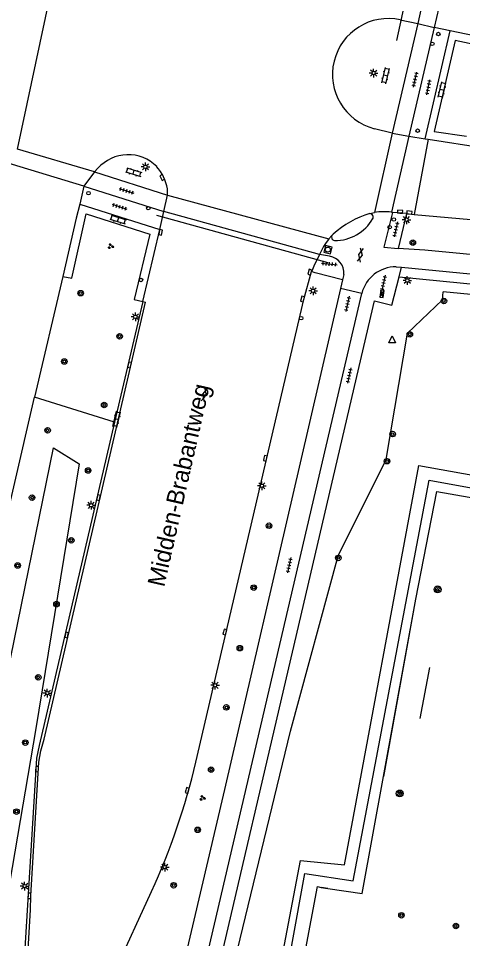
# Model space of a CAD drawing. Extents: x 130998 to 133001, y 398999 to 403002.
# Drawn here: x 132831.9 to 132896.2, y 399348.3 to 399481.4 of the extents above; entities that cross this region are included whole.
import ezdxf

# ---------------------------------------------------------------- set-up
doc = ezdxf.new("R2010")
doc.units = 0
for name, color, linetype in [('bs-afsc-ballenvanger', 7, 'Continuous'), ('bs-afsc-doel', 7, 'Continuous'), ('bs-afsc-poort', 7, 'Continuous'), ('bs-symb-sproeier', 7, 'Continuous'), ('gg-afsc-hekwerk', 7, 'Continuous'), ('gg-anno-openbare ruimte label', 7, 'Continuous'), ('gg-knt-verharding', 7, 'Continuous'), ('gg-knt-verharding nz', 7, 'Continuous'), ('gt-grn-groengrens', 7, 'Continuous'), ('gt-grn-weggrens', 7, 'Continuous'), ('gt-grn-weggrens revisie', 7, 'Continuous'), ('gt-knt-lijn portaal', 7, 'Continuous'), ('gt-symb-boom', 7, 'Continuous'), ('gt-symb-drukknoppaal', 7, 'Continuous'), ('gt-symb-gesloten verharding', 7, 'Continuous'), ('gt-symb-groenvak', 7, 'Continuous'), ('gt-symb-klinker verharding', 7, 'Continuous'), ('gt-symb-kolk', 7, 'Continuous'), ('gt-symb-lichtmast', 7, 'Continuous'), ('gt-symb-rioolschacht', 7, 'Continuous'), ('gt-symb-tegel verharding', 7, 'Continuous'), ('gt-symb-verkeersregelinstallatiekast', 7, 'Continuous'), ('gt-symb-verkeersregelinstallatiepaal', 7, 'Continuous'), ('gt-symb-waterafsluiter', 7, 'Continuous')]:
    doc.layers.add(name, color=color, linetype=linetype)

# ---------------------------------------------------------------- blocks, each defined once
blk = doc.blocks.new('gt0-KL1')
at = {"layer": 'gt-symb-klinker verharding'}
for p, q in [((-1.15, 0.3), (1.15, 0.3)), ((-1, -0.3), (-1, 0.3)), ((-0.5, 0.3), (-0.5, 0.45)), ((0, -0.3), (0, 0.3)), ((0.5, 0.3), (0.5, 0.45)), ((1, -0.3), (1, 0.3)), ((-1.15, -0.3), (1.15, -0.3)), ((-0.5, -0.45), (-0.5, -0.3)), ((0.5, -0.45), (0.5, -0.3))]:
    blk.add_line(p, q, dxfattribs=at)
blk = doc.blocks.new('gt0-TEG1')
at = {"layer": 'gt-symb-tegel verharding'}
for p, q in [((-1.12, 0), (1.12, 0)), ((-0.9, -0.25), (-0.9, 0.25)), ((-0.45, -0.25), (-0.45, 0.25)), ((0, -0.25), (0, 0.25)), ((0.45, -0.25), (0.45, 0.25)), ((0.9, -0.25), (0.9, 0.25))]:
    blk.add_line(p, q, dxfattribs=at)
blk = doc.blocks.new('gt0-LMAST')
at = {"layer": 'gt-symb-lichtmast'}
for p, q in [((-0.18, 0.17), (-0.45, 0.44)), ((-0.01, 0.25), (-0.01, 0.62)), ((0.17, 0.17), (0.44, 0.44)), ((-0.26, 0), (-0.63, 0)), ((-0.18, -0.18), (-0.45, -0.45)), ((-0.01, -0.25), (-0.01, -0.63)), ((0.44, -0.45), (0.17, -0.18)), ((0.24, 0), (0.62, 0))]:
    blk.add_line(p, q, dxfattribs=at)
blk.add_circle((-0.01, 0), 0.25, dxfattribs=at)
blk = doc.blocks.new('gt0-DPAAL')
at = {"layer": 'gt-symb-drukknoppaal'}
blk.add_circle((0, 0), 0.25, dxfattribs=at)
blk = doc.blocks.new('gt0-VIPAAL')
at = {"layer": 'gt-symb-verkeersregelinstallatiepaal'}
blk.add_circle((0, 0), 0.25, dxfattribs=at)
blk = doc.blocks.new('gt0-KOLK')
at = {"layer": 'gt-symb-kolk'}
blk.add_lwpolyline([(0, 0), (0.37, 0), (0.37, 0.4), (-0.38, 0.4), (-0.38, 0), (0, 0)], dxfattribs=at)
blk = doc.blocks.new('gt0-RS')
at = {"layer": 'gt-symb-rioolschacht'}
blk.add_lwpolyline([(-0.5, -0.5), (0.5, -0.5), (0.5, 0.5), (-0.5, 0.5)], close=True, dxfattribs=at)
blk.add_circle((0, 0), 0.375, dxfattribs=at)
blk = doc.blocks.new('gt0-GESVH1')
at = {"layer": 'gt-symb-gesloten verharding'}
for p, q in [((-0.99, -0.26), (0.01, 0.24)), ((0.01, -0.26), (-0.99, 0.24)), ((0.01, 0.24), (1.01, -0.26)), ((1.01, 0.24), (0.01, -0.26))]:
    blk.add_line(p, q, dxfattribs=at)
blk = doc.blocks.new('gt0-BOOM')
at = {"layer": 'gt-symb-boom'}
for radius in [0.4, 0.2]:
    blk.add_circle((0, 0), radius, dxfattribs=at)
blk = doc.blocks.new('gt0-GRVAK')
at = {"layer": 'gt-symb-groenvak'}
for p, q in [((-0.11, 0.19), (-0.23, 0.24)), ((-0.18, 0.15), (0.09, 0.15)), ((-0.09, 0.21), (-0.16, 0.32)), ((-0.05, 0.21), (-0.05, 0.39)), ((0, 0.21), (0.06, 0.32)), ((0.01, 0.19), (0.13, 0.24)), ((0.26, -0.05), (0.2, 0.06)), ((0.3, -0.05), (0.3, 0.13)), ((0.35, -0.05), (0.41, 0.06)), ((-0.24, -0.23), (-0.36, -0.18)), ((-0.32, -0.26), (-0.05, -0.26)), ((-0.23, -0.21), (-0.29, -0.09)), ((-0.18, -0.2), (-0.18, -0.02)), ((-0.14, -0.21), (-0.07, -0.09)), ((-0.12, -0.23), (0, -0.18)), ((0.24, -0.07), (0.12, -0.02)), ((0.17, -0.11), (0.44, -0.11)), ((0.37, -0.07), (0.49, -0.02))]:
    blk.add_line(p, q, dxfattribs=at)
blk = doc.blocks.new('gt0-VRIKST')
at = {"layer": 'gt-symb-verkeersregelinstallatiekast'}
for p, q in [((-0.5, -0.25), (0.5, 0.25)), ((-0.5, 0.25), (0.5, -0.25))]:
    blk.add_line(p, q, dxfattribs=at)
blk.add_lwpolyline([(0.5, 0.25), (-0.5, 0.25), (-0.5, -0.25), (0.5, -0.25)], close=True, dxfattribs=at)
blk = doc.blocks.new('gt0-WAFSL')
at = {"layer": 'gt-symb-waterafsluiter'}
for p, q in [((-0.5, -0.33), (0, 0.67)), ((0, 0.67), (0.5, -0.33)), ((0.5, -0.33), (-0.5, -0.33))]:
    blk.add_line(p, q, dxfattribs=at)
blk = doc.blocks.new('bs0-SPROEIER')
at = {"layer": 'bs-symb-sproeier'}
for p, q in [((-0.34, 0.2), (0.2, -0.34)), ((-0.21, 0.35), (0.34, -0.2)), ((0.03, 0.4), (0.4, 0.03)), ((-0.4, -0.03), (-0.03, -0.4))]:
    blk.add_line(p, q, dxfattribs=at)
blk.add_circle((0, 0), 0.5, dxfattribs=at)

msp = doc.modelspace()

# ---------------------------------------------------------------- linework, layer by layer
at = {"layer": 'bs-afsc-ballenvanger'}
msp.add_line((132884.76, 399371.7), (132889.37, 399397.36), dxfattribs=at)
at = {"layer": 'bs-afsc-doel'}
msp.add_line((132890.01, 399380.09), (132891.4, 399387.46), dxfattribs=at)
at = {"layer": 'bs-afsc-poort'}
msp.add_line((132875.68, 399355.68), (132876.66, 399355.53), dxfattribs=at)
at = {"layer": 'gg-afsc-hekwerk'}
msp.add_line((132876.66, 399355.53), (132875.68, 399355.68), dxfattribs=at)
for points in [[(132889.37, 399397.36), (132892.4, 399412.94), (132925.72, 399407.1)], [(132876.66, 399355.53), (132881.63, 399354.77), (132889.37, 399397.36)], [(132863.07, 399291.46), (132875.15, 399355.78), (132875.68, 399355.68)]]:
    msp.add_lwpolyline(points, dxfattribs=at)
at = {"layer": 'gg-knt-verharding'}
for p, q in [((132887.12, 399481.18), (132889.68, 399480.63)), ((132889.68, 399480.63), (132885.96, 399464.75)), ((132892.06, 399480.08), (132888.38, 399464.33)), ((132889.68, 399480.63), (132892.06, 399480.08)), ((132894.36, 399479.6), (132892.06, 399480.08)), ((132890.71, 399463.97), (132894.36, 399479.6)), ((132904.81, 399477.39), (132894.36, 399479.6)), ((132885.96, 399464.75), (132883.38, 399465.42)), ((132885.96, 399464.75), (132888.38, 399464.33)), ((132888.38, 399464.33), (132890.71, 399463.97)), ((132890.71, 399463.97), (132891.19, 399463.9)), ((132891.19, 399463.9), (132901.04, 399462.38)), ((132843.38, 399459.7), (132842.87, 399459.18)), ((132842.87, 399459.18), (132841.36, 399457.11)), ((132842.87, 399459.18), (132853.47, 399455.79)), ((132841.36, 399457.11), (132840.75, 399454.5)), ((132841.36, 399457.11), (132852.94, 399453.43)), ((132852.94, 399453.43), (132853.47, 399455.79)), ((132853.47, 399455.79), (132853.47, 399456.73)), ((132840.75, 399454.5), (132852.35, 399450.84)), ((132852.35, 399450.84), (132852.94, 399453.43)), ((132888.01, 399453.13), (132886.02, 399453.32)), ((132888.01, 399453.13), (132886.85, 399448.1)), ((132888.01, 399453.13), (132889.15, 399453.03)), ((132849.87, 399440.41), (132852.35, 399450.84)), ((132877.43, 399450.16), (132877.22, 399449.95)), ((132877.47, 399449.29), (132877.63, 399449.25)), ((132876.9, 399446.97), (132875.44, 399447.21)), ((132886.52, 399445.45), (132887.3, 399445.38)), ((132838.29, 399444.06), (132834.22, 399426.59)), ((132878.97, 399444.35), (132878.78, 399443.55)), ((132886.95, 399443.97), (132939.03, 399438.92)), ((132878.78, 399443.55), (132878.48, 399442.29)), ((132846.17, 399289.96), (132881.56, 399441.59)), ((132878.48, 399442.29), (132872.63, 399417.07)), ((132881.56, 399441.59), (132878.48, 399442.29)), ((132849.87, 399440.41), (132845.79, 399422.95)), ((132849.87, 399440.41), (132850.28, 399440.31))]:
    msp.add_line(p, q, dxfattribs=at)
for points in [[(132904.81, 399477.39), (132904.51, 399476.16), (132895.09, 399478.2), (132892.04, 399465.01), (132896.73, 399464.33)], [(132840.75, 399454.5), (132840.24, 399452.47), (132838.29, 399444.06)], [(132838.29, 399444.06), (132839.61, 399443.78), (132841.68, 399453.12), (132850.91, 399450.18), (132848.62, 399440.7), (132849.87, 399440.41)], [(132886.02, 399453.32), (132884.77, 399448.28), (132886.85, 399448.1)], [(132889.15, 399453.03), (132905.03, 399451.62), (132922.15, 399450.06)], [(132916.23, 399445.37), (132901.79, 399446.8), (132890.67, 399447.85), (132886.85, 399448.1)], [(132875.44, 399447.21), (132874.63, 399445.55), (132874.31, 399444.83), (132874.29, 399444.75)], [(132887.3, 399445.38), (132939.45, 399440.33), (132957.32, 399437.98), (132974.21, 399435.67), (132990.03, 399433.38), (133000, 399431.89)], [(132848.15, 399289.52), (132883.39, 399440.5), (132885.93, 399439.9), (132886.95, 399443.97)], [(132857.54, 399373.78), (132873.2, 399440.72), (132874.29, 399444.75)], [(132878.78, 399443.55), (132874.8, 399444.59), (132874.29, 399444.75)], [(132831.89, 399331.89), (132832.43, 399331.86), (132833.61, 399352.42), (132833.67, 399354.45), (132834.83, 399373.77), (132835.14, 399375.45), (132835.58, 399377.1), (132847.93, 399430.32), (132850.28, 399440.31)], [(132762.64, 399000), (132764.86, 399018.61), (132773.1, 399080.84), (132777.39, 399111.89), (132787.45, 399180.57), (132799.49, 399253.49), (132821.57, 399368.18), (132821.05, 399368.32), (132828.33, 399401.27), (132834.22, 399426.59)], [(132845.79, 399422.95), (132834.86, 399376.22), (132834.48, 399374.36), (132831.89, 399331.89)], [(132872.63, 399417.07), (132861.68, 399369.83), (132843.19, 399290.95)], [(132772.83, 399000), (132775.07, 399017.52), (132784.71, 399079.82), (132793.52, 399126.23), (132804.32, 399176.71), (132840.62, 399332.15), (132851.14, 399355.1)]]:
    msp.add_lwpolyline(points, dxfattribs=at)
for centre, radius, start, end in [((132885.42, 399473.26), 8.1, 77.84, 166.2632), ((132885.42, 399473.26), 8.1, 166.2849, 255.411), ((132847.76, 399455.82), 5.84, 45.0487, 138.4289), ((132846.25, 399455.18), 7.38, 12.1299, 40.3162), ((132886.66, 399439.98), 13.74, 106.552, 132.2085), ((132882.7, 399452.65), 0.508, 331.076, 84.2901), ((132877.7, 399455.53), 6.28, 269.4295, 330.1834), ((132877.67, 399449.74), 0.497, 154.988, 246.6135), ((132876.54, 399444.56), 2.44, 354.9696, 81.5951), ((132886.51, 399440.35), 5.1, 89.9511, 165.903), ((132761.39, 399396.27), 98.75, 335.3566, 346.836)]:
    msp.add_arc(centre, radius, start, end, dxfattribs=at)
at = {"layer": 'gg-knt-verharding nz'}
for p, q in [((132892.98, 399496.5), (132889.68, 399480.63)), ((132895.51, 399495.14), (132892.06, 399480.08)), ((132885.96, 399464.75), (132883.4, 399453.29)), ((132888.38, 399464.33), (132885.85, 399453.34)), ((132842.87, 399459.18), (132831.72, 399462.47)), ((132841.36, 399457.11), (132829.43, 399460.7)), ((132853.47, 399455.79), (132876.79, 399449.47)), ((132875.44, 399447.21), (132852.94, 399453.43)), ((132882.75, 399453.15), (132883.4, 399453.29)), ((132885.85, 399453.34), (132886.02, 399453.32)), ((132877.22, 399449.95), (132876.79, 399449.47))]:
    msp.add_line(p, q, dxfattribs=at)
for centre, radius, start, end in [((132884.79, 399445.17), 8.24, 82.5999, 99.6925), ((132883.48, 399443.96), 8.67, 140.4841, 157.954)]:
    msp.add_arc(centre, radius, start, end, dxfattribs=at)
at = {"layer": 'gt-grn-groengrens'}
msp.add_line((132845.79, 399422.95), (132834.22, 399426.59), dxfattribs=at)
for points in [[(132846.79, 399277.41), (132871.24, 399378.25), (132878.15, 399403.62), (132885.09, 399417.58), (132888.18, 399435.85), (132893.23, 399440.68), (132893.34, 399441.82)], [(132968.46, 399433.54), (132938.54, 399437.48), (132893.34, 399441.82)], [(132846.79, 399277.41), (132849.47, 399276.97), (132849.56, 399277.12), (132850.42, 399278.24), (132851.9, 399278.69), (132853.73, 399278.33), (132854.18, 399276.39), (132856.78, 399275.98), (132872.7, 399359.57), (132879.05, 399358.94), (132889.84, 399416.71), (132961.48, 399403.86), (132963.58, 399415.25), (132974.36, 399413.48), (132975.53, 399419.89), (132980.55, 399418.98), (132980.57, 399419.09)], [(132802.26, 399226.05), (132797.53, 399226.68), (132817.25, 399322.97), (132836.97, 399419.26), (132840.67, 399416.95), (132834.38, 399378.64), (132823.69, 399316.06), (132819.29, 399291.8), (132802.26, 399226.05)], [(132858.19, 399274.24), (132873.33, 399357.67), (132880.32, 399356.61), (132891.32, 399414.6), (132962.62, 399401.59)]]:
    msp.add_lwpolyline(points, dxfattribs=at)
at = {"layer": 'gt-grn-weggrens'}
for p, q in [((132831.72, 399462.47), (132841.4, 399507.69)), ((132886.95, 399443.97), (132887.3, 399445.38))]:
    msp.add_line(p, q, dxfattribs=at)
at = {"layer": 'gt-grn-weggrens revisie'}
msp.add_line((132891.19, 399463.9), (132889.15, 399453.03), dxfattribs=at)
at = {"layer": 'gt-knt-lijn portaal'}
for p, q in [((132886.64, 399478.2), (132891.24, 399499.17)), ((132851.87, 399452.89), (132876.65, 399446.07))]:
    msp.add_line(p, q, dxfattribs=at)

# ---------------------------------------------------------------- block references
at = {"layer": 'bs-symb-sproeier'}
for p in [(132892.54, 399398.78), (132887.05, 399369.26)]:
    msp.add_blockref('bs0-SPROEIER', p, dxfattribs=at)
at = {"layer": 'gt-symb-boom'}
for p in [(132888.95, 399448.93), (132840.88, 399441.63), (132893.45, 399440.5), (132846.52, 399435.39), (132888.51, 399435.68), (132838.52, 399431.75), (132844.28, 399425.45), (132836.1, 399421.79), (132886.02, 399421.25), (132885.22, 399417.32), (132841.96, 399415.98), (132833.85, 399412.05), (132868.14, 399407.99), (132839.53, 399405.88), (132831.76, 399402.23), (132878.16, 399403.33), (132865.93, 399399.04), (132837.39, 399396.64), (132863.92, 399390.28), (132834.75, 399386.06), (132861.97, 399381.71), (132832.87, 399376.62), (132859.76, 399372.7), (132831.6, 399366.64), (132857.82, 399364), (132854.34, 399355.98), (132887.3, 399351.64), (132895.18, 399350.09)]:
    msp.add_blockref('gt0-BOOM', p, dxfattribs=at)
at = {"layer": 'gt-symb-drukknoppaal'}
for p, rotation in [((132891.77, 399477.69), 76.54507187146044), ((132850.67, 399453.91), -107.78678798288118), ((132885.59, 399451.18), -13.339410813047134)]:
    msp.add_blockref('gt0-DPAAL', p, dxfattribs=dict(at, rotation=rotation))
at = {"layer": 'gt-symb-gesloten verharding'}
for p, rotation in [((132881.38, 399447.17), -102.77124256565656), ((132858.8, 399426.94), 76.7561979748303)]:
    msp.add_blockref('gt0-GESVH1', p, dxfattribs=dict(at, rotation=rotation))
at = {"layer": 'gt-symb-groenvak'}
for p in [(132845.22, 399448.41), (132858.51, 399368.6)]:
    msp.add_blockref('gt0-GRVAK', p, dxfattribs=at)
at = {"layer": 'gt-symb-klinker verharding'}
for p, rotation in [((132885.02, 399473.09), 76.06098564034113), ((132893.19, 399471.02), 76.88085536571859), ((132848.56, 399459.13), -16.622396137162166), ((132846.31, 399452.27), -17.09430559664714), ((132846.1, 399423.37), 76.00541608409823)]:
    msp.add_blockref('gt0-KL1', p, dxfattribs=dict(at, rotation=rotation))
at = {"layer": 'gt-symb-kolk'}
for p, rotation in [((132852.87, 399458.45), 116.30869593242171), ((132887.09, 399453.22), -5.2930571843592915), ((132888.44, 399453.09), -5.293057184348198), ((132852.26, 399450.46), -103.93901435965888), ((132874.25, 399444.62), 74.81021282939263), ((132873.2, 399440.72), 74.86552497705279), ((132848.14, 399431.22), 76.88085536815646), ((132867.41, 399417.77), -103.17492660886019), ((132843.67, 399412.02), 76.93666266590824), ((132839.05, 399392.14), 76.99249520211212), ((132861.54, 399392.64), -103.29958432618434), ((132834.78, 399372.79), 86.55950512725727), ((132856.1, 399369.74), -107.27542027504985), ((132833.67, 399354.45), 88.10803457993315)]:
    msp.add_blockref('gt0-KOLK', p, dxfattribs=dict(at, rotation=rotation))
at = {"layer": 'gt-symb-lichtmast'}
for p in [(132883.28, 399473.47), (132850.26, 399459.91), (132888.04, 399452.26), (132888.16, 399443.46), (132874.52, 399441.97), (132848.81, 399438.21), (132867.11, 399413.77), (132842.41, 399410.95), (132860.33, 399384.91), (132836.06, 399383.78), (132853.06, 399358.61), (132832.78, 399355.86)]:
    msp.add_blockref('gt0-LMAST', p, dxfattribs=at)
at = {"layer": 'gt-symb-rioolschacht', "rotation": -13.299584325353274}
msp.add_blockref('gt0-RS', (132876.66, 399447.93), dxfattribs=at)
at = {"layer": 'gt-symb-tegel verharding'}
for p, rotation in [((132889.29, 399472.52), 76.88085536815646), ((132891.2, 399471.4), 78.52151796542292), ((132847.53, 399456.45), -17.764323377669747), ((132846.52, 399454.14), -17.764323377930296), ((132886.5, 399450.85), -102.2428595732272), ((132876.87, 399445.85), -5.163306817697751), ((132884.71, 399443.13), -102.2428595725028), ((132879.5, 399440.08), -101.95064726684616), ((132879.74, 399429.72), -101.88275886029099), ((132871.04, 399402.29), -102.59095061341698)]:
    msp.add_blockref('gt0-TEG1', p, dxfattribs=dict(at, rotation=rotation))
at = {"layer": 'gt-symb-verkeersregelinstallatiekast', "rotation": 82.84795923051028}
msp.add_blockref('gt0-VRIKST', (132884.49, 399441.53), dxfattribs=at)
at = {"layer": 'gt-symb-verkeersregelinstallatiepaal'}
for p, rotation in [((132892.64, 399479.11), 76.54507187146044), ((132889.64, 399465.13), -13.339410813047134), ((132842.01, 399456.09), -109.41496635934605), ((132886.2, 399452.28), -13.339410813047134), ((132849.62, 399443.54), -13.644818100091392), ((132872.79, 399438.02), 166.35518189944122)]:
    msp.add_blockref('gt0-VIPAAL', p, dxfattribs=dict(at, rotation=rotation))
at = {"layer": 'gt-symb-waterafsluiter'}
msp.add_blockref('gt0-WAFSL', (132885.96, 399434.79), dxfattribs=at)

# ---------------------------------------------------------------- texts
at = {"layer": 'gg-anno-openbare ruimte label'}
msp.add_text('Midden-Brabantweg', height=2.5, rotation=77.2, dxfattribs=at).set_placement((132852.96, 399399.02))

doc.saveas('drawing.dxf')
